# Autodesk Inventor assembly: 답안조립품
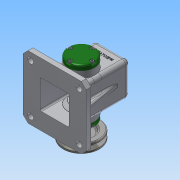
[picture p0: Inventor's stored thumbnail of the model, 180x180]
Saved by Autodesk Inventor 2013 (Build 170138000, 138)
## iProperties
Created: 2016-02
Part Number: 답안조립품
Document SubType Name: Assembly
Designer: Administrator
Author: Administrator
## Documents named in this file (16)
- C:\Users\Administrator\Desktop\460212V1005\답안조립품.iam
- C:\Users\Administrator\Desktop\460212V1005\본체.ipt
- C:\Users\Administrator\Desktop\460212V1005\V벨트풀리.ipt
- C:\Users\Administrator\Desktop\460212V1005\고정핀 1.2 x 10.ipt
- C:\Users\Administrator\Desktop\460212V1005\뒤커버.ipt
- C:\Users\Administrator\Desktop\460212V1005\링크.ipt
- C:\Users\Administrator\Desktop\460212V1005\멈춤나사 M3x8.ipt
- C:\Users\Administrator\Desktop\460212V1005\베어링 12 x 32 x 10.ipt
- C:\Users\Administrator\Desktop\460212V1005\볼트 M4 x 12.ipt
- C:\Users\Administrator\Desktop\460212V1005\부시.ipt
- C:\Users\Administrator\Desktop\460212V1005\슬라이드.ipt
- C:\Users\Administrator\Desktop\460212V1005\앞커버.ipt
- C:\Users\Administrator\Desktop\460212V1005\오일실 12 25 7.ipt
- C:\Users\Administrator\Desktop\460212V1005\키 4 x 4 x 10.ipt
- C:\Users\Administrator\Desktop\460212V1005\편심축.ipt
- C:\Users\Administrator\Desktop\460212V1005\핀 5 x 18.ipt
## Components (11 placed, 4 different names)
1. V벨트풀리:1
2. 고정핀 1.2 x 10:1
3. 핀 5 x 18:1
4. ISO 4762 M4 x 12:1
5. ISO 4762 M4 x 12:3
6. ISO 4762 M4 x 12:4
7. ISO 4762 M4 x 12:5
8. ISO 4762 M4 x 12:2
9. ISO 4762 M4 x 12:6
10. ISO 4762 M4 x 12:7
11. ISO 4762 M4 x 12:8
